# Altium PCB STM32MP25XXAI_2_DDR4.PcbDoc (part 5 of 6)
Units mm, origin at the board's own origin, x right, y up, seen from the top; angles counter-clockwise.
Board outline 172 x 137 mm, 4 copper layers (Top Layer, Signal Layer 1, Signal Layer 2, Bottom Layer), stack 1.614 mm thick; 241 components, 153 nets, 1312 pads, 924 vias.
Unrouted connection lines stored in the file: 13.
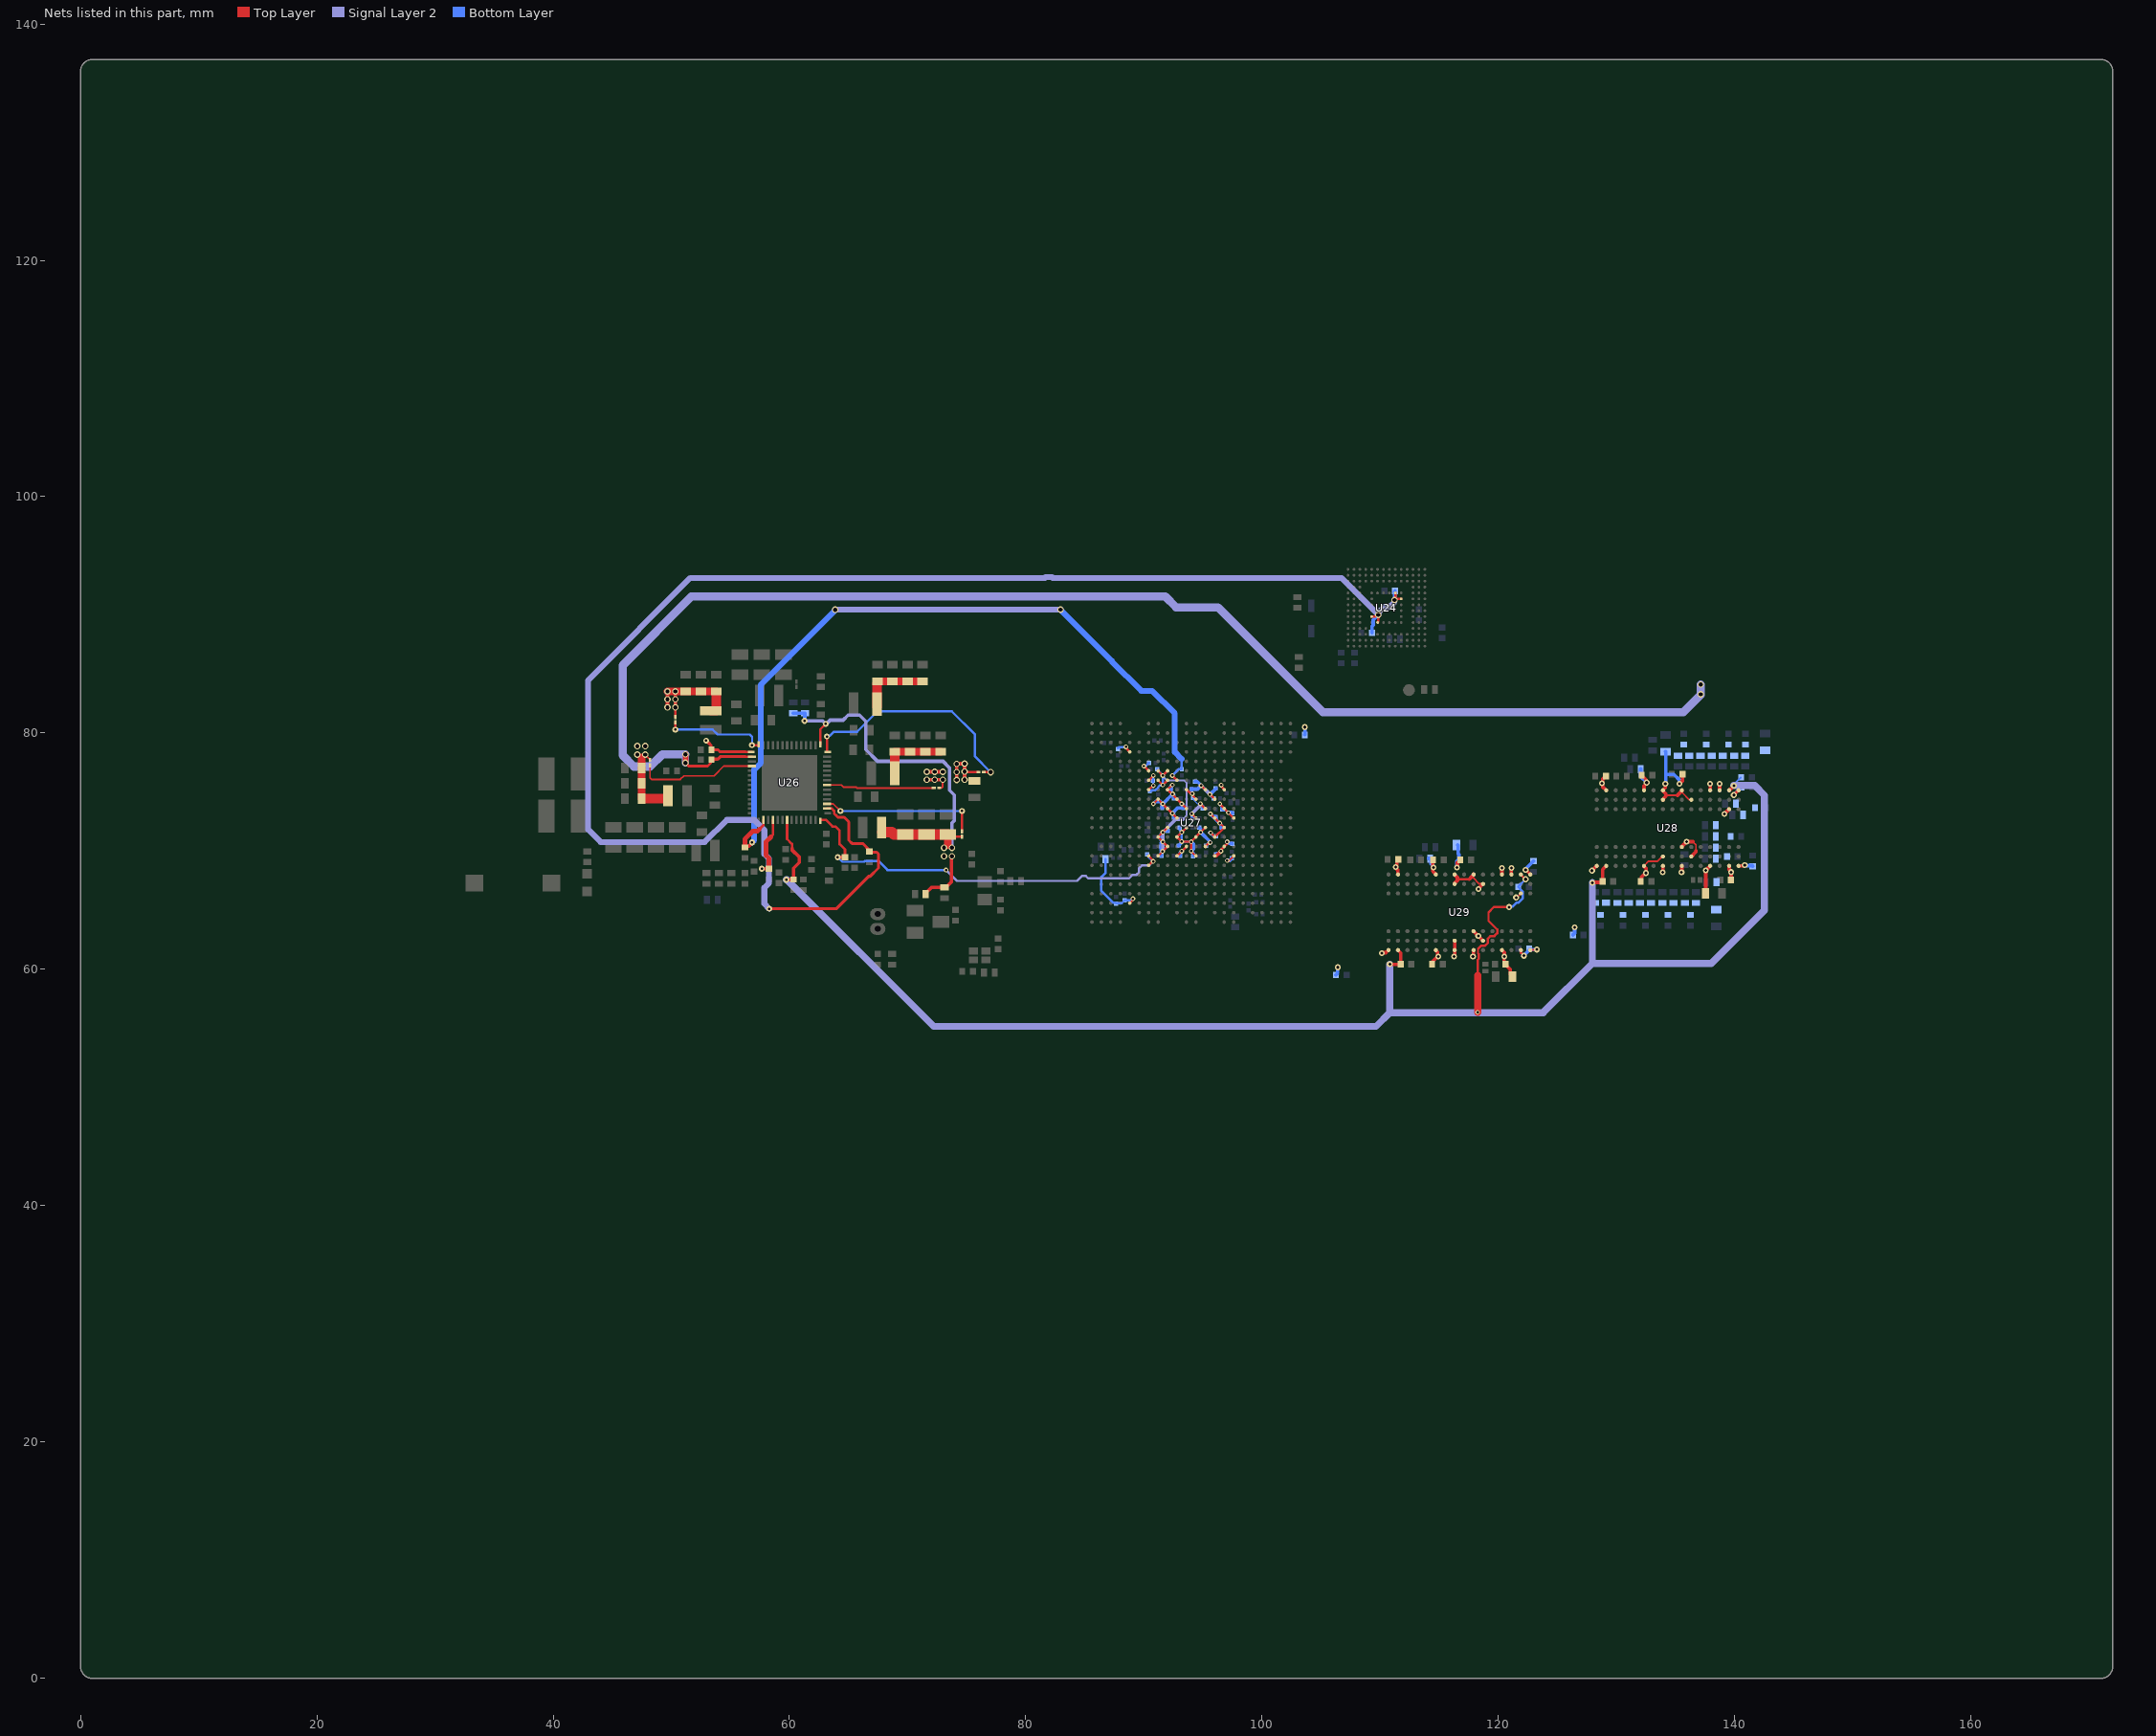
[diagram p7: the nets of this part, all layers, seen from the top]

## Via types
v1: diameter 0.55, hole 0.35, Top Layer to Bottom Layer, 432 vias
v2: diameter 0.4, hole 0.2, Top Layer to Bottom Layer, tented both sides, 202 vias
v3: diameter 0.5, hole 0.2, Top Layer to Bottom Layer, 146 vias
v4: diameter 0.5, hole 0.25, Top Layer to Bottom Layer, 144 vias

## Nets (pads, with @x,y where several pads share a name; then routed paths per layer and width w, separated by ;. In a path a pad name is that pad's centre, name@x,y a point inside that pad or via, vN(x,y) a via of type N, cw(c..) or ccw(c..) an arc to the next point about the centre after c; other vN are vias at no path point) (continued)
VDD_DDR: C39.2 C41.2 C48.2 C50.2 C51.2 C53.2 C54.1 C55.2 C56.2 C57.2 C58.2 C59.2 C60.2 C76.2 C77.2 C80.2 C82.2 C84.2 C85.2 C93.2 C94.2 C99.2 C200.2 C202.2 C236.2 C238.2 C247.2 C261.2 C262.2 C264.2 C276.2 C278.2 C279.2 L5.2 LNK8.2 R300.2 R302.2 U26.43 U27.K15 U27.L14 U27.L16 U27.M15 U27.N14 U27.P15 U27.R14 U27.R16 U28.A1 U28.A9 U28.B3 U28.B9 U28.C1 U28.D1 U28.D9 U28.F2 U28.F8 U28.G1 U28.G7 U28.G9 U28.J1 U28.J2 U28.J8 U28.J9 U28.L1 U28.L9 U28.R1 U28.T9 U29.A1 U29.A9 U29.B3 U29.B9 U29.C1 U29.D1 U29.D9 U29.F2 U29.F8 U29.G1 U29.G7 U29.G9 U29.J1 U29.J2 U29.J8 U29.J9 U29.L1 U29.L9 U29.R1 U29.T9 | length 80.3
  Top Layer w0.09: U29.J8@116.269,62.399 U29.J8@116.269,62.424 ; 135.525,74.975 U28.G1@135.525,75.094
  Top Layer w0.1: U27.R16@97.575,69.6 U27.R16@97.6,69.6
  Top Layer w0.15: v1(47.798,78.165) 48.2,77.763 LNK8.2@48.2,77.723 ; 117.718,67.815 117.757,67.815 117.797,67.775 117.845,67.775 118.389,67.232 118.694,67.232 U29.F2@118.7,67.225 ; U29.G1@117.9,67.998 U29.G1@117.9,68.025 ; v4@121.5,66.054 121.514,66.054 121.885,66.425 U29.B3@121.9,66.425 ; U28.L9@132.325,68.75 132.325,68.775 132.7,69.15 133.475,69.15 U28.J8@133.936,69.611 ; 134.158,74.728 135.167,74.728 ; 135.525,74.975 136.15,74.35 U28.F2@136.325,74.35 ; 136.45,70.8 136.725,70.525 136.725,70.05
  Top Layer w0.2: v2@95.6,73.15 v2(95.625,73.15) 95.65,73.15 U27.L14@96,72.8 v2(96.42,72.379) ; v2@95.625,71.575 U27.N14@96,71.2 U27.M15@96.8,72 v2@96.421,72.379 ; v2@96.4,74 U27.K15@96.8,73.6 v2(97.15,73.25) ; v2(96.525,70) 96.563,70.038 96.563,70.163 U27.P15@96.8,70.4 97.05,70.65 v2(97.05,70.8) ; v2(97.05,69.2) 97.2,69.2 U27.R16@97.6,69.6 ; v2@97.125,73.275 v2(97.15,73.25) ; U27.L16@97.6,72.8 v2(97.15,73.25) ; 116.526,67.625 117.535,67.625 ; U29.B9@121.9,61.625 121.906,61.619 121.906,61.394 v4(122.15,61.15) ; U29.A9@122.7,61.625 122.725,61.65 123.225,61.65 v4(123.25,61.675)
  Top Layer w0.21: 56.275,78.4 U26.43@56.825,78.4
  Top Layer w0.25: 53.195,79.125 53.199,79.125 53.345,78.979 53.345,78.685 C39.2@53.455,78.575 ; C39.2@53.505,78.575 53.975,78.575 54.15,78.4 56.275,78.4
  Top Layer w0.3: v3@52.944,79.376 53.195,79.125 ; U27.R14@96,69.6 96.125,69.6 v2(96.525,70) ; v4@110.105,61.41 v4(110.144,61.372) 110.182,61.41 110.459,61.41 110.673,61.625 U29.T9@110.7,61.625 ; U29.R1@111.5,68.025 111.481,68.044 111.481,68.415 111.3,68.596 v4(111.3,68.65) 111.3,68.704 111.42,68.824 111.42,69.195 C77.2@111.525,69.3 ; C94.2@114.356,60.385 C94.2@114.394,60.422 ; C76.2@114.45,69.197 114.45,68.6 114.45,68.3 114.7,68.05 U29.L1@114.7,68.025 ; C94.2@114.468,60.697 114.846,61.075 v4(114.9,61.075) 114.862,61.113 114.862,61.436 114.7,61.598 U29.L9@114.7,61.625 ; v4(116.25,61.075) 116.3,61.125 U29.J9@116.3,61.625 U29.J8@116.3,62.425 ; U29.J2@116.3,67.225 116.32,67.244 116.32,67.317 116.526,67.524 116.526,67.625 116.526,67.772 116.3,67.998 U29.J1@116.3,68.025 ; v4@116.492,68.629 116.538,68.675 116.538,69.013 116.775,69.25 C80.2@116.775,69.275 ; 117.535,67.625 117.535,67.632 117.718,67.815 U29.G1@117.9,67.998 ; v4(117.85,61.075) 117.85,61.129 117.891,61.17 117.891,61.615 U29.G9@117.9,61.625 ; U29.G1@117.881,68.044 U29.G1@117.9,68.025 ; v4@117.896,61.08 v4@117.9,61.084 ; U29.G7@117.9,63.225 117.9,63.213 117.913,63.213 v4(118.3,62.825) ; v4@118.3,62.813 v4(118.3,62.825) ; v4(118.325,66.8) 118.325,66.837 118.7,67.213 U29.F2@118.7,67.225 ; U29.F8@118.7,62.425 v4(118.3,62.825) ; U29.D9@120.3,61.625 120.5,61.425 v4(120.5,61.075) 120.47,61.045 120.47,60.53 C93.2@120.825,60.175 ; U29.D1@120.3,68.025 v4(120.3,68.575) ; C93.2@120.6,60.425 120.6,60.4 121.005,59.995 121.005,59.57 C99.2@121.175,59.4 ; U29.C1@121.1,68.025 v4(121.1,68.575) ; v4(122.3,68.425) U29.A1@122.7,68.025 ; v4(127.927,68.35) 128.305,68.728 U28.T9@128.332,68.728 ; C51.2@129.095,76.371 129.095,76.346 128.813,76.065 128.813,75.788 v4(128.775,75.75) 128.813,75.712 128.813,75.462 U28.R1@129.125,75.15 ; C84.2@132.025,67.425 C84.2@132.05,67.45 132.1,67.499 132.1,67.8 132.478,68.178 132.497,68.178 v4@132.5,68.175 ; C50.2@132.125,76.425 132.125,76.4 132.23,76.295 132.255,76.295 132.512,76.038 132.512,75.838 v4(132.55,75.8) 132.55,75.749 132.325,75.524 U28.L1@132.325,75.15 ; U28.L9@132.332,68.701 132.5,68.533 v4@132.5,68.175 ; v4(132.5,68.15) v4@132.5,68.175 ; v4(133.9,68.2) 133.925,68.225 U28.J9@133.925,68.75 ; U28.J1@133.925,75.15 134.125,75.35 v4(134.125,75.7) ; U28.J2@133.932,74.328 133.951,74.347 133.951,74.42 134.158,74.627 134.158,74.728 134.158,74.875 U28.J1@133.932,75.101 ; 135.167,74.728 135.167,74.735 U28.G1@135.525,75.094 ; v4(135.325,75.7) 135.575,75.95 C48.2@135.575,76.375 ; v4(135.5,68.2) 135.525,68.225 U28.G9@135.525,68.75 ; U28.G7@135.525,70.35 135.525,70.4 v4(135.925,70.8) 136.45,70.8 ; U28.F8@136.325,69.55 136.725,69.95 136.725,70.05 ; C85.2@137.525,66.425 137.542,66.442 137.542,68.367 v4(137.55,68.375) 137.903,68.728 U28.D9@137.932,68.728 ; U28.D1@137.932,75.128 v4@137.932,75.678 ; U28.C1@138.732,75.128 v4@138.732,75.678 ; v4(139.125,73.15) U28.B3@139.525,73.55 ; U28.B9@139.525,68.75 139.535,68.74 139.535,68.445 139.7,68.279 v4(139.7,68.225) 139.688,68.213 139.688,67.563 C82.2@139.675,67.55 ; v4(139.925,74.75) U28.A1@140.325,75.15 ; U28.A9@140.325,68.75 140.335,68.76 140.73,68.76 140.796,68.825 v4(140.85,68.825)
  Top Layer w0.64: C202.2@47.475,74.45 C41.2@47.475,75.75 C200.2@47.475,77.05 ; 47.475,77.495 47.475,77.925
  Top Layer w0.8: C202.2@47.7,74.45 L5.2@49.475,74.45
  Signal Layer 2 w0.3: v2@96.356,72.394 96.406,72.394 v2@96.425,72.375
  Bottom Layer w0.09: C279.2@140.55,75.425 C279.2@140.575,75.4
  Bottom Layer w0.2: v2@96.4,74 96.4,73.946 96.549,73.796 96.549,73.599 C60.2@96.624,73.524 ; C60.2@96.631,73.524 96.704,73.452 96.933,73.452 97.135,73.25 v2(97.15,73.25) ; v2@97.125,73.275 v2(97.15,73.25) ; v2@97.15,73.23 v2(97.15,73.25)
  Bottom Layer w0.3: v2@95.6,71.575 95.9,71.275 C55.2@96.1,71.275 ; v2@95.6,73.15 v2(95.625,73.15) ; v2@95.627,73.15 v2(95.625,73.15) ; C59.2@96.1,69.725 96.175,69.8 96.308,69.8 96.508,70 v2(96.525,70) ; v2(96.42,72.379) 96.394,72.379 96.124,72.649 96.124,72.687 96.099,72.712 96.099,72.85 C56.2@96.074,72.875 96.049,72.9 95.875,72.9 v2(95.625,73.15) ; v2@96.425,72.375 96.425,72.347 96.549,72.223 96.549,71.999 C57.2@96.574,71.974 ; v2@97.023,70.8 v2(97.05,70.8) 97.077,70.8 97.227,70.65 97.45,70.65 C54.1@97.475,70.625 ; v2(97.05,69.2) 97.069,69.219 97.269,69.219 C53.2@97.45,69.4 ; v2@97.125,73.275 97.425,73.275 C58.2@97.5,73.2 ; C276.2@103.62,79.846 103.625,79.851 v4(103.625,80.5) ; C264.2@106.25,59.525 106.4,59.675 v4(106.4,60.175) ; R300.2@114.1,69.38 114.205,69.275 114.305,69.175 114.305,68.947 114.462,68.79 114.462,68.663 v4(114.5,68.625) ; v4@116.5,68.575 116.492,68.583 116.492,69.16 116.65,69.318 116.65,69.732 116.596,69.787 116.596,70.479 C236.2@116.55,70.525 ; v4@122.075,61.1 122.65,61.675 v4(123.25,61.675) ; v4(122.3,68.425) 122.339,68.463 122.339,68.538 122.95,69.15 C247.2@122.975,69.15 ; C261.2@126.3,62.9 126.45,63.05 v4(126.45,63.55) ; R302.2@132.05,76.95 132.05,76.3 v4(132.55,75.8) ; v4(134.125,75.7) 134.166,75.741 134.166,76.487 ; C278.2@134.15,78.425 134.166,78.409 134.166,76.873 134.166,76.487 ; 134.166,76.114 134.166,76.487 ; v4(135.325,75.7) 135.325,76.025 134.864,76.487 134.166,76.487 ; v4(139.925,74.75) 139.925,74.8 140.55,75.425 C279.2@140.438,75.313 ; v4@140.875,68.775 141.475,68.775 C238.2@141.525,68.725
  other v1: 47.123,78.165 47.123,78.89 47.798,78.89
  other v2: 95.65,71.55 96.425,74
  other v3: 52.95,79.348
  other v4: 121.5,66.08 116.5,68.625 137.925,75.7 138.725,75.7
VDD_DDR_FB: LNK8.1 U26.46 | length 10.2
  Top Layer w0.15: LNK8.1@48.2,77.273 48.2,76.19 48.317,76.073 50.767,76.073 51.067,76.373 51.737,76.373 51.739,76.375 53.627,76.375 54.452,77.2 U26.46@56.83,77.2
VDD_EMMC: C177.2 C180.2 C190.1 U24.E6 U24.F5 U24.J10 U24.K9 U26.16 | length 133.6
  Top Layer w0.2: U24.E6@109.275,89.85 109.58,89.85 109.73,90 v1(109.825,90) ; U24.F5@109.775,89.35 109.775,89.358 109.825,89.408 v1@109.825,89.85 ; v1(111.2,91.25) v1@111.275,91.325 ; U24.J10@111.275,91.85 111.275,91.42 111.267,91.412 111.267,91.333 v1@111.275,91.325 ; U24.K9@111.775,91.35 111.395,91.35 111.362,91.317 111.283,91.317 v1@111.275,91.325
  Top Layer w0.21: U26.16@63.17,73.6 63.6,73.6 63.788,73.412 63.788,73.188 63.934,73.041
  Top Layer w0.25: v3(58.3,65.125) 63.96,65.125 66.7,67.865 66.822,67.865 67.535,68.578 67.535,69.764 67.389,69.91 66.805,69.91 C190.1@66.75,69.965 ; 63.932,73.038 64.098,72.872 64.628,72.872 65.025,72.475 65.025,70.925 65.3,70.65 66.195,70.65 C190.1@66.75,70.095
  Signal Layer 2 w0.5: v3(58.3,65.125) 57.872,65.553 57.872,66.908 58.265,67.301 58.265,69.369 57.872,69.762 57.872,71.786 57.009,72.649 54.703,72.649 52.827,70.773 44.024,70.773 42.958,71.839 42.958,84.457 51.616,93.115 81.606,93.115 81.691,93.2 82.209,93.2 82.294,93.115 85.406,93.115 85.416,93.125 85.934,93.125 85.944,93.115 106.726,93.115 v1@109.678,90.163 ; v1(109.825,90) 109.835,90.01 109.835,90.196 110.259,90.62 110.475,90.62 110.737,90.62 111.2,91.083 v1(111.2,91.25)
  Bottom Layer w0.3: C180.2@109.3,88.475 109.3,89.049 109.4,89.149 109.4,89.575 v1(109.825,90) ; v1(111.2,91.25) 111.225,91.275 111.225,92 C177.2@111.25,92.025
VDD_SDCARD: C142.1 U26.4 | length 5.1
  Top Layer w0.21: 58.425,71.2 58.6,71.375 U26.4@58.6,72.63
  Top Layer w0.3: v3(57.665,68.51) C142.1@58.275,68.51
  Top Layer w0.4: C142.1@58.275,68.51 58.275,69.393 58.01,69.658 58.01,70.785 58.425,71.2
VDDA1V8_AON: C189.2 C234.2 U26.14 U27.R7 U27.T7 | length 35.8
  Top Layer w0.2: U27.T7@90.4,68.8 90.687,69.087 90.757,69.087 v2(90.795,69.125) 90.795,69.178 90.4,69.573 U27.R7@90.4,69.6
  Top Layer w0.21: U26.14@62.6,72.63 63.11,72.63 63.648,72.092 63.887,72.092 64.245,71.734 64.245,70.602 64.7,70.147 C189.2@64.7,69.49
  Top Layer w0.3: v3(64.09,69.49) C189.2@64.7,69.49
  Signal Layer 2 w0.2: v2(73.253,68.406) 73.259,68.406 74.183,67.482 84.342,67.482 84.76,67.9 85.091,67.9 85.292,67.699 88.734,67.699 89.034,68 89.2,68 89.366,68 89.6,68.234 89.6,68.566 89.835,68.8 90.47,68.8 v2(90.795,69.125) v2@90.726,69.125
  Bottom Layer w0.2: v3(64.09,69.49) 64.48,69.1 66.321,69.1 66.392,69.171 67.535,69.171 68.3,68.406 v2(73.253,68.406) ; C234.2@90.275,69.735 90.441,69.569 90.441,69.443 90.76,69.125 v2(90.795,69.125)
VDDCORE: C1.1 C2.2 C3.2 C4.1 C5.2 C6.2 C22.2 C23.2 C24.2 C66.2 C69.2 C70.2 C183.2 L2.2 LNK2.2 R249.1 U27.D5 U27.F7 U27.G7 U27.H7 U27.H9 U27.J8 U27.J10 U27.K9 U27.K11 U27.L10 | length 26.2
  Top Layer w0.2: C22.2@71.275,84.375 C22.2@71.323,84.423 ; v1@74.87,76.685 LNK2.2@75.98,76.685 ; v2(88.475,78.825) 88.475,78.725 U27.D5@88.8,78.4 ; v2(90,77.2) U27.F7@90.4,76.8 U27.F7@90.425,76.8 ; U27.H7@90.4,75.2 90.425,75.2 90.775,75.55 v2(90.8,75.55) ; U27.G7@90.4,76 v2(90.8,76.4) ; v2(90.8,74) U27.J8@91.2,74.4 v2(91.6,74) v2(92.4,73.2) U27.L10@92.8,72.8 ; v2(92.4,75.6) U27.H9@92,75.2 v2@92.425,74.775 ; v2(92.425,74.85) v2@92.425,74.775 ; U27.K11@93.6,73.6 v2(93.2,74) U27.J10@92.8,74.4 v2@92.425,74.775
  Top Layer w0.3: v1@74.151,77.404 v1(74.826,77.404) v1(74.826,76.729) ; v1(74.156,76.024) v1(74.156,76.699) v1(74.156,77.374) ; v1(74.826,76.054) v1(74.826,76.729) ; v1@74.87,76.685 v1(74.826,76.729)
  Top Layer w0.64: C183.2@67.45,84.375 C24.2@68.725,84.375 C23.2@70,84.375 C22.2@71.275,84.375
  Top Layer w0.8: L2.2@67.415,82.2 L2.2@67.415,82.45 C183.2@67.415,84.173
  Bottom Layer w0.2: C70.2@87.8,78.7 87.9,78.8 88.038,78.8 v2@88.4,78.8 ; v2(90,77.2) 90.038,77.238 90.188,77.238 C66.2@90.425,77.475 ; v2(90.8,75.55) 90.777,75.572 90.777,75.948 C69.2@90.755,75.97 90.777,75.992 90.777,76.378 v2(90.8,76.4)
  Bottom Layer w0.3: v2(90.8,74) 91,74.2 91.4,74.2 v2(91.6,74) ; C3.2@91.55,73.65 91.55,73.95 v2(91.6,74) ; v2(92.4,75.6) 92.275,75.475 C4.1@92.275,75.25 92.275,75 v2(92.425,74.85) ; C1.1@92.55,72.825 92.55,73.05 v2(92.4,73.2) 92.85,73.65 C2.2@93.326,73.65 93.325,73.875 v2(93.2,74) ; C5.2@92.551,74.475 92.55,74.725 v2(92.425,74.85) ; v2(91.6,74) 92.425,74.825 v2(92.425,74.85)
VDDCORE_FB: LNK2.1 U26.28 | length 19.9
  Top Layer w0.2: U26.28@63.17,78.4 v3(63.17,79.7) ; LNK2.1@76.444,76.687 v1@77.031,76.685
  Bottom Layer w0.2: v3(63.17,79.7) 63.227,79.757 63.401,79.757 63.754,80.111 65.734,80.111 67.457,81.833 73.744,81.833 75.675,79.902 75.675,78.041 v1(77.033,76.683)
VDDCPU: C13.1 C14.2 C15.2 C16.1 C17.2 C25.2 C26.2 C27.2 C28.2 C31.2 L3.2 LNK4.1 U27.H11 U27.H13 U27.H15 U27.J12 U27.J14 U27.K13 U27.L12 | length 21.1
  Top Layer w0.2: LNK4.1@50.35,81.35 v1(50.35,82.173) ; U27.H11@93.6,75.2 93.627,75.2 93.924,74.903 94.052,74.903 94.128,74.827 94.128,74.699 94.4,74.427 U27.J12@94.4,74.4 ; v2(94.045,73.155) U27.L12@94.4,72.8 ; v2(94.775,74.005) 95.18,73.6 U27.K13@95.2,73.6 ; v2(94.845,75.555) U27.H13@95.2,75.2 ; v2(95.595,74.805) U27.J14@96,74.4 ; v2(96.54,75.591) 96.578,75.553 96.578,75.449 96.8,75.227 U27.H15@96.8,75.2
  Top Layer w0.3: v1(49.675,82.173) v1(49.675,82.848) v1(49.675,83.523) v1(50.35,83.523) v1(50.35,82.848) v1(50.35,82.173)
  Top Layer w0.64: v1(49.675,83.523) 49.675,83.525 C27.2@51.2,83.525 C28.2@52.5,83.525 C26.2@53.8,83.525
  Top Layer w0.8: L3.2@53.35,81.875 53.8,81.875 53.8,83.173
  Signal Layer 2 w0.3: v2(94.045,73.155) 94.756,73.866 94.756,73.986 v2(94.775,74.005) ; v2(94.845,75.555) v2(95.595,74.805)
  Bottom Layer w0.1: C14.2@94.15,74.48 94.15,74.379 94.524,74.005 v2(94.775,74.005)
  Bottom Layer w0.2: v2(94.045,73.155) 94.045,72.855 C31.2@94.125,72.775 ; v2@94.775,73.978 v2(94.775,74.005) ; C13.1@94.95,73.625 94.95,73.803 ; v2(95.595,74.805) 95.633,74.767 95.633,74.692 C15.2@95.875,74.45
  Bottom Layer w0.3: v2(94.095,74.865) 94.095,74.892 94.05,74.937 94.05,75.225 C25.2@94.025,75.25 94.548,75.25 v2@94.853,75.555 ; C17.2@94.325,75.875 94.525,75.875 v2(94.845,75.555) ; v2@94.775,73.978 94.95,73.803 ; v2(95.595,74.805) C16.1@96.095,75.305
VDDCPU_FB: LNK4.2 U26.42 | length 8.6
  Top Layer w0.2: v3(50.35,80.29) LNK4.2@50.35,80.9 ; v3(56.825,78.975) U26.42@57.395,78.975
  Bottom Layer w0.2: v3@50.37,80.287 53.499,80.287 53.914,79.872 56.643,79.872 56.845,79.67 v3@56.845,78.972
VDDGPU: C7.2 C8.2 C9.2 C10.2 C11.1 C12.2 C34.2 C35.2 C36.2 C37.2 L4.2 LNK7.2 U27.M11 U27.M13 U27.N10 U27.N12 U27.P13 U27.R12 | length 21.3
  Top Layer w0.15: LNK7.2@72.675,75.35 72.682,75.358 72.885,75.358 72.973,75.445 v1(72.973,76.038)
  Top Layer w0.2: C35.2@73.05,78.393 C35.2@73.098,78.345 ; U27.M11@93.6,72 v2(93.2,71.6) U27.N10@92.8,71.2 93.197,70.803 93.997,70.803 v2(94,70.8) ; U27.R12@94.4,69.6 v2(94,70) v2(94,70.8) ; U27.P13@95.2,70.4 95.487,70.687 95.562,70.687 v2(95.6,70.725) ; U27.M13@95.2,72 v2(94.8,71.6) v2(94,70.8)
  Top Layer w0.3: v1(71.623,76.038) v1(72.298,76.038) v1(72.973,76.038) ; v1(71.623,76.713) v1(72.298,76.713) v1(72.973,76.713)
  Top Layer w0.64: C37.2@68.9,78.4 C36.2@70.2,78.4 C34.2@71.5,78.4 C35.2@72.8,78.4
  Top Layer w0.8: L4.2@68.925,76.6 68.925,78.073
  Bottom Layer w0.2: C9.2@93.025,72 93.025,71.775 v2(93.2,71.6) 93.197,71.598 93.197,70.808 93.195,70.805 93.197,70.803 93.997,70.803 v2(94,70.8) ; v2(95.6,70.725) v2@95.61,70.715
  Bottom Layer w0.3: C10.2@92.95,70.48 93.176,70.706 93.176,70.786 v2@93.195,70.805 ; v2(94,70.8) 94.175,70.625 94.175,70.175 v2(94,70) 94.2,69.8 C12.2@94.2,69.575 ; C7.2@94.675,72 94.8,71.875 v2(94.8,71.6) 94.833,71.567 95.581,70.819 95.581,70.744 v2(95.6,70.725) 95.581,70.706 95.506,70.706 C11.1@95.25,70.45
  other v2: 93.2,70.805
VDDGPU_FB: LNK7.1 U26.21 | length 9.3
  Top Layer w0.15: U26.21@63.05,75.6 64.383,75.6 64.56,75.423 65.64,75.423 65.713,75.35 LNK7.1@72.225,75.35
VDDIO: C19.2 C44.1 C45.2 C46.2 C47.1 C52.2 C73.2 C74.2 C186.2 C187.2 L6.2 LNK11.2 R27.2 R67.2 R260.2 R261.2 U26.29 U27.F8 U27.F9 U27.G8 U27.G9 U27.M9 U27.N8 U27.P9 U27.P11 U27.R8 U27.R10 | length 61.4
  Top Layer w0.2: U26.29@62.6,79.045 62.6,80.298 v3(63.075,80.773) ; C186.2@73.4,71.4 73.585,71.215 LNK11.2@74.6,71.215 ; U27.R8@91.2,69.6 v2(91.575,69.975) U27.P9@92,70.4 v2(91.6,70.8) U27.N8@91.2,71.2 v2(91.6,71.6) U27.M9@92,72 ; U27.G8@91.2,76 91.599,75.6 U27.G9@92,76 ; U27.F8@91.2,76.8 v2(91.6,76.4) U27.F9@92,76.8 ; U27.R10@92.8,69.6 v2(93.2,70) U27.P11@93.6,70.4
  Top Layer w0.3: R67.2@71.525,66.375 71.525,66.44 72.01,66.925 R27.2@73.125,66.925 73.23,67.03 73.339,67.03 73.712,67.402 73.712,69.52 v1(73.752,69.56) ; v1(73.077,69.56) v1@73.125,69.512
  Top Layer w0.64: 73.4,70.525 C186.2@73.4,70.955
  Top Layer w0.9: L6.2@67.85,71.6 68.65,71.6 68.85,71.4 C187.2@69.8,71.4 C19.2@71.6,71.4 C186.2@73.4,71.4
  Signal Layer 2 w0.15: v2(91.599,75.599) 91.971,75.971 91.962,75.98 ; v2@91.6,76.338 v2@91.6,76.342 ; v2(91.6,76.4) v2@91.6,76.342 ; 93.301,72.703 93.608,73.01 93.608,75.783 93.411,75.98 91.962,75.98 ; v2@91.6,76.342 91.962,75.98
  Signal Layer 2 w0.3: v3(61.284,81.027) 62.799,81.027 63.05,80.776 v3@63.075,80.776 ; v3(63.075,80.773) 63.129,80.773 63.44,81.084 64.543,81.084 64.973,81.513 65.931,81.513 66.455,80.989 66.455,78.601 67.456,77.6 72.999,77.6 73.551,77.048 73.551,75.156 73.951,74.756 73.951,72.573 73.752,72.375 v1(73.752,70.285) ; v2(91.575,69.975) 91.6,70 v2(91.6,71.6) 92.703,72.703 93.301,72.703
  Bottom Layer w0.2: C74.2@90.5,75.05 90.575,75.125 90.667,75.125 90.692,75.15 90.931,75.15 90.946,75.165 90.981,75.165 91.2,75.384 91.2,75.419 91.342,75.561 91.561,75.561 v2(91.599,75.599) 91.6,76.4 91.6,76.45 C73.2@91.125,76.925
  Bottom Layer w0.3: R260.2@60.33,81.68 R261.2@61.305,81.68 61.294,81.669 61.294,81.038 v3(61.284,81.027) ; C44.1@91.475,69.6 91.475,69.875 v2(91.575,69.975) 91.475,70.075 91.475,70.675 v2(91.6,70.8) 91.475,70.925 91.475,71.475 91.725,71.725 C46.2@92.025,71.725 ; C45.2@93.075,69.6 93.075,69.875 v2(93.2,70) v2@93.225,70
  other v1: 73.077,70.285
VDDIO_FB: LNK11.1 U26.17 | length 13.4
  Top Layer w0.15: U26.17@63.17,74 63.7,74 64.303,73.397 v3(64.315,73.397)
  Top Layer w0.2: LNK11.1@74.6,71.665 v3(74.6,73.4)
  Bottom Layer w0.15: v3(64.315,73.397) v3@74.597,73.397
VDDIO_SDCARD: C71.2 C217.1 U26.2 U27.G10 | length 65.5
  Top Layer w0.2: v2(92.4,76.4) U27.G10@92.8,76
  Top Layer w0.21: 57.459,71.873 57.8,72.214 U26.2@57.8,72.63
  Top Layer w0.3: C217.1@56.225,70.38 56.27,70.425 56.559,70.425 56.835,70.701 v3(56.835,70.737)
  Top Layer w0.4: C217.1@56.225,70.32 56.225,70.38 56.225,71.015 56.899,71.69 57.275,71.69 57.459,71.873
  Signal Layer 2 w0.5: v1(63.865,90.43) 63.867,90.432 82.942,90.432 v1(82.945,90.435)
  Bottom Layer w0.2: v2(92.4,76.4) 92.95,76.95 C71.2@93.201,76.95 93.201,77.799
  Bottom Layer w0.5: v3(56.835,70.737) 57.009,70.911 57.009,76.91 57.581,77.482 57.581,81.596 57.575,81.601 57.575,82.099 57.581,82.104 57.581,84.092 63.855,90.367 63.855,90.42 v1(63.865,90.43) ; v1@82.945,90.444 v1(82.945,90.435) 87.294,86.086 87.294,86.055 89.779,83.57 90.696,83.57 92.605,81.661 92.605,78.395 93.2,77.8
VPP_DDR: C83.2 C91.1 C95.2 C245.2 C277.2 U26.7 U28.B1 U28.R9 U29.B1 U29.R9 | length 143.8
  Top Layer w0.09: U28.B1@139.526,75.127 U28.B1@139.602,75.127
  Top Layer w0.2: 118.242,59.475 118.242,60.789 118.35,60.898 118.35,61.271 118.275,61.346 118.275,61.73 118.545,62 118.879,62 119.115,62.236 119.115,62.6 119.334,62.819 119.665,62.819 119.9,63.053 119.9,63.368 119.166,64.102 119.166,64.816 119.62,65.27 v4(120.9,65.27) ; U29.B1@121.9,68.011 v4@122.287,67.625
  Top Layer w0.21: U26.7@59.8,72.63 59.8,71.025 60.215,70.61 60.215,70.253
  Top Layer w0.28: v4(110.809,60.424) C95.2@111.49,60.424 ; C95.2@111.49,60.425 C95.2@111.725,60.425 111.725,61.4 U29.R9@111.5,61.625 U29.R9@111.5,61.575 ; C83.2@128.825,67.45 128.825,68.45 U28.R9@129.125,68.75
  Top Layer w0.3: v3(59.74,67.58) C91.1@60.35,67.58 ; 60.215,70.253 60.215,70.118 60.835,69.498 60.835,69.035 60.35,68.55 C91.1@60.35,67.73 ; v4@127.925,67.325 127.96,67.36 128.735,67.36 C83.2@128.825,67.45 ; U28.B1@139.532,75.128 v4@139.932,75.528
  Top Layer w0.6: v2(118.242,56.366) 118.242,59.475
  Signal Layer 2 w0.6: v3(59.74,67.58) 59.793,67.58 72.203,55.171 109.646,55.171 110.809,56.334 ; v4(110.809,60.424) 110.809,56.334 ; 123.801,56.334 110.809,56.334 ; 123.801,56.351 127.95,60.5 ; v4(127.95,67.325) 127.95,60.5 ; v4@139.93,75.546 141.709,75.546 142.522,74.733 142.522,65.002 138.02,60.5 127.95,60.5
  Bottom Layer w0.09: v4(139.925,75.55) v4@139.925,75.65 ; C277.2@140.5,76.225 C277.2@140.55,76.225
  Bottom Layer w0.15: v4@139.925,75.65 C277.2@140.5,76.225
  Bottom Layer w0.2: v4(120.9,65.27) 120.957,65.327 121.217,65.327 121.519,65.63 121.686,65.63 122.072,66.016 122.072,66.553 121.83,66.795 121.83,66.82 C245.2@121.675,66.975 121.675,67 v4(122.3,67.625)
VREF+: C67.2 C68.2 R269.2 U27.Y5 | length 6.6
  Top Layer w0.2: U27.Y5@88.8,65.6 89.037,65.837 89.037,65.942 v2(89.076,65.981)
  Bottom Layer w0.2: R269.2@86.754,69.315 86.754,68.159 86.402,67.808 86.402,66.63 87.387,65.645 87.585,65.645 87.63,65.6 88.125,65.6 C68.2@88.375,65.85 88.904,65.85 89.035,65.981 v2(89.076,65.981)
VTT_DDR: C40.2 C211.2 C226.2 C239.2 C254.2 C255.2 C256.2 C257.2 C258.2 C259.2 C280.2 C281.2 C282.2 C283.2 C284.2 R253.2 R254.2 R255.2 R256.2 R257.2 R258.2 R259.2 R263.2 R264.2 R265.2 R266.2 R268.2 R271.2 R273.2 R275.2 R276.2 R277.2 R278.2 R279.2 R280.2 R281.2 R282.2 R283.2 R284.2 U26.44 | length 120.6
  Top Layer w0.21: 56.275,78 U26.44@56.83,78
  Top Layer w0.25: v1(51.2,78.198) v1@51.202,78.196 ; v1@51.225,77.473 v1(51.202,77.473) 51.475,77.2 53.075,77.2 53.32,77.445 53.32,77.635 53.435,77.75 C40.2@53.505,77.75 ; C40.2@53.51,77.635 53.665,77.79 53.94,77.79 54.15,78 56.275,78
  Top Layer w0.5: v1(51.202,77.473) v1@51.202,78.196
  Signal Layer 2 w0.6: v1@51.2,77.475 v1(51.2,78.198)
  Signal Layer 2 w0.7: v1(51.2,78.198) 49.244,78.198 48.209,77.163 46.837,77.163 45.883,78.117 45.883,85.733 51.699,91.549 91.801,91.549 92.714,90.636 96.269,90.636 105.136,81.769 135.665,81.769 137.125,83.229 v1(137.125,83.275) v1(137.125,84.1)
pads on no net: U24.A1 U24.A2 U24.A7 U24.A8 U24.A9 U24.A10 U24.A11 U24.A12 U24.A13 U24.A14 U24.B1 U24.B7 U24.B8 U24.B9 U24.B10 U24.B11 U24.B12 U24.B13 U24.B14 U24.C1 U24.C3 U24.C5 U24.C7 U24.C8 U24.C9 U24.C10 U24.C11 U24.C12 U24.C13 U24.C14 U24.D1 U24.D2 U24.D3 U24.D4 U24.D12 U24.D13 U24.D14 U24.E1 U24.E2 U24.E3 U24.E5 U24.E8 U24.E9 U24.E10 U24.E12 U24.E13 U24.E14 U24.F1 U24.F2 U24.F3 U24.F10 U24.F12 U24.F13 U24.F14 U24.G1 U24.G2 U24.G3 U24.G10 U24.G12 U24.G13 U24.G14 U24.H1 U24.H2 U24.H3 U24.H12 U24.H13 U24.H14 U24.J1 U24.J2 U24.J3 U24.J12 U24.J13 U24.J14 U24.K1 U24.K2 U24.K3 U24.K6 U24.K7 U24.K10 U24.K12 U24.K13 U24.K14 U24.L1 U24.L2 U24.L3 U24.L12 U24.L13 U24.L14 U24.M1 U24.M2 U24.M3 U24.M7 U24.M8 U24.M9 U24.M10 U24.M11 U24.M12 U24.M13 U24.M14 U24.N1 U24.N3 U24.N6 U24.N7 U24.N8 U24.N9 U24.N10 U24.N11 U24.N12 U24.N13 U24.N14 U24.P1 U24.P2 U24.P7 U24.P8 U24.P9 U24.P10 U24.P11 U24.P12 U24.P13 U24.P14 U27.A2 U27.A3 U27.A4 U27.A7 U27.A8 U27.A11 U27.A12 U27.A15 U27.A16 U27.A21 U27.AA1 U27.AA2 U27.AA3 U27.AA4 U27.AA6 U27.AA7 U27.AA8 U27.AA10 U27.AA11 U27.AA12 U27.AA14 U27.AA15 U27.AA16 U27.AA18 U27.AA19 U27.AA20 U27.AA21 U27.AB2 U27.AB3 U27.AB4 U27.AB7 U27.AB8 U27.AB11 U27.AB12 U27.AB15 U27.AB16 U27.AB19 U27.AB20 U27.AB21 U27.B1 U27.B2 U27.B3 U27.B4 U27.B5 U27.B7 U27.B8 U27.B9 U27.B11 U27.B12 U27.B13 U27.B15 U27.B16 U27.B17 U27.B20 U27.B21 U27.C1 U27.C2 U27.C3 U27.C5 U27.C6 U27.C8 U27.C9 U27.C10 U27.C11 U27.C12 U27.C13 U27.C14 U27.C15 U27.C16 U27.C17 U27.C20 U27.D1 U27.D2 U27.D3 U27.D4 U27.D6 U27.D7 U27.D8 U27.D9 U27.D10 U27.D11 U27.D12 U27.D13 U27.D14 U27.D15 U27.D16 U27.D19 U27.E3 U27.E4 U27.E6 U27.E7 U27.E8 U27.E9 U27.E10 U27.E11 U27.E12 U27.E13 U27.E14 U27.E15 U27.E18 U27.F2 U27.F3 U27.F4 U27.F5 U27.F11 U27.F12 U27.F13 U27.F14 U27.F15 U27.G1 U27.G2 U27.G3 U27.G4 U27.G5 U27.G11 U27.G12 U27.G13 U27.G14 U27.G16 U27.H1 U27.H2 U27.H3 U27.H4 U27.H5 U27.H6 U27.J3 U27.J4 U27.J5 U27.J6 U27.J7 U27.J18 U27.K2 U27.K3 U27.K4 U27.K5 U27.K6 U27.K7 U27.K17 U27.L1 U27.L2 U27.L3 U27.L4 U27.L5 U27.L6 U27.L7 U27.L20 U27.M1 U27.M2 U27.M3 U27.M4 U27.M5 U27.M6 U27.N3 U27.N4 U27.N5 U27.N6 U27.P2 U27.P3 U27.P4 U27.P5 U27.R3 U27.R4 U27.R5 U27.R6 U27.T1 U27.T2 U27.T8 U27.T9 U27.T10 U27.T11 U27.T12 U27.T13 U27.T14 U27.T15 U27.T17 U27.T18 U27.U4 U27.U5 U27.U8 U27.U9 U27.U10 U27.U11 U27.U12 U27.U13 U27.U14 U27.U15 U27.U16 U27.U18 U27.U19 U27.V4 U27.V5 U27.V6 U27.V8 U27.V9 U27.V10 U27.V11 U27.V12 U27.V13 U27.V14 U27.V15 U27.V16 U27.V17 U27.W1 U27.W2 U27.W3 U27.W4 U27.W6 U27.W7 U27.W9 U27.W10 U27.W11 U27.W12 U27.W13 U27.W14 U27.W15 U27.W17 U27.Y1 U27.Y3 U27.Y4 U27.Y6 U27.Y7 U27.Y8 U27.Y9 U27.Y10 U27.Y11 U27.Y12 U27.Y13 U27.Y14 U27.Y15 U27.Y17 U27.Y18 U27.Y20 U28.P9 U28.T7 U29.P9 U29.T7
copper on no net: | length 335.7
  Top Layer w0.09: 81.172,76.702 85.898,76.702 86.105,76.495 88.305,76.495 88.8,76 ; 81.614,76.882 86.261,76.882 86.343,76.8 86.4,76.8 ; 81.76,77.09 86.513,77.09 86.803,76.8 87.2,76.8 ; 82.23,77.27 86.59,77.27 86.775,77.085 87.332,77.085 87.342,77.075 87.575,76.842 87.59,76.827 87.973,76.827 88,76.8 ; 82.334,77.52 86.693,77.52 86.898,77.315 87.427,77.315 87.437,77.305 87.657,77.085 88.515,77.085 88.8,76.8 ; 82.986,77.7 87.043,77.7 87.143,77.6 87.2,77.6 ; 83.083,77.935 87.665,77.935 88,77.6 ; 83.395,70.522 83.453,70.522 83.53,70.445 85.911,70.445 86.233,70.123 86.549,70.123 86.777,69.895 87.556,69.895 87.76,70.099 ; 83.448,70.265 85.754,70.265 86.124,69.895 86.522,69.895 86.817,69.6 87.2,69.6 ; 83.537,70.707 83.619,70.625 86.175,70.625 86.4,70.4 ; 83.604,70.895 83.694,70.805 86.412,70.805 86.695,70.522 86.695,70.28 86.9,70.075 87.406,70.075 87.731,70.4 88,70.4 ; 83.673,71.08 83.758,70.995 86.477,70.995 87.032,70.44 87.16,70.44 87.2,70.4 ; 83.685,78.115 85.718,78.115 86.003,78.4 86.4,78.4 ; 83.748,71.26 83.833,71.175 86.551,71.175 87.031,70.695 88.295,70.695 88.8,71.2 ; 83.789,78.365 85.565,78.365 85.6,78.4 ; 83.877,71.64 83.982,71.535 86.75,71.535 87.045,71.24 87.16,71.24 87.2,71.2 ; 84.075,71.875 84.235,71.715 86.827,71.715 87.047,71.495 88.295,71.495 88.8,72 ; 84.174,72.075 84.249,72 ; 84.615,68.995 85.224,68.995 85.354,69.125 87.525,69.125 88,69.6 ; 84.65,68.41 85.613,68.41 86.003,68.8 86.4,68.8 ; 84.862,74.565 86.439,74.565 86.939,75.065 87.011,75.065 87.146,75.2 87.2,75.2 ; 85.472,78.675 85.482,78.685 86.603,78.685 86.875,78.413 86.875,78.3 87.06,78.115 87.715,78.115 88,78.4 ; 85.472,78.925 85.482,78.915 86.642,78.915 87.157,78.4 87.2,78.4 ; 86.115,75.475 86.125,75.475 86.4,75.2 ; 86.865,75.665 87.2,76 ; 87.359,70.885 87.361,70.885 87.683,70.885 87.998,71.2 ; 87.424,60.877 89.925,63.377 89.925,64.197 90.105,64.377 90.105,65.305 90.4,65.6 ; 87.634,82.95 89.145,81.439 89.145,80.673 89.52,80.298 89.52,79.693 89.885,79.328 89.885,78.115 90.4,77.6 ; 87.634,60.832 90.105,63.303 90.105,64.122 90.4,64.417 90.4,64.8 ; 87.738,83.2 89.395,81.543 89.395,81.439 89.395,80.91 89.394,80.909 89.394,80.776 89.75,80.42 89.75,79.788 90.115,79.424 90.115,78.273 90.273,78.115 90.347,78.115 90.4,78.168 90.4,78.4 ; 87.796,81.5 88.106,81.19 88.285,81.011 88.285,79.715 88.8,79.2 ; 87.826,82.15 88.715,81.261 88.715,80.495 89.085,80.125 89.085,78.915 89.6,78.4 ; 87.87,60.813 90.4,63.343 90.4,64 ; 87.9,81.75 88.535,81.115 88.535,81.011 88.535,79.853 88.673,79.715 88.747,79.715 88.8,79.768 88.8,80 ; 87.93,82.4 88.965,81.365 88.965,80.599 89.335,80.229 89.335,79.053 89.473,78.915 89.547,78.915 89.6,78.968 89.6,79.2 ; 88.124,70.099 88.405,70.38 88.78,70.38 88.8,70.4 ; 89.745,63.452 89.745,64.271 89.925,64.451 89.925,65.925 90.4,66.4 ; v2@90.8,78 91.2,77.6 ; v2(90.846,66.845) 91.2,67.2 ; v2(90.846,67.645) 91.2,68 ; v2@90.865,65.226 v2(90.846,65.245) 91.2,65.6 ; v2(91.525,66.825) 91.575,66.825 91.95,67.2 92,67.2 ; 92.145,63.204 92.145,65.071 92.505,65.431 92.505,65.722 92.505,66.905 92.8,67.2 ; 92.325,62.976 92.325,64.997 92.603,65.275 92.744,65.275 92.8,65.331 92.8,65.6 ; 92.505,62.82 92.505,64.922 92.678,65.095 92.969,65.095 93.12,65.247 93.12,66.08 92.8,66.4 ; 92.765,62.66 92.765,64.346 92.825,64.406 92.825,64.775 92.8,64.8 ; v2(93.05,66.775) 93.294,67.019 93.364,67.019 93.545,67.2 93.6,67.2 ; 93.29,82.424 93.29,80.31 93.6,80 ; 93.6,76 v2@94,76.4 ; v2(93.898,66.003) 93.93,66.035 93.93,66.75 94.38,67.2 94.4,67.2 ; 93.925,62.425 93.925,65.173 94.105,65.353 94.105,65.722 94.25,65.868 94.25,66.239 94.4,66.389 94.4,66.4 ; v2(93.95,67.6) 94.35,68 94.4,68 ; 94.105,62.105 94.105,64.122 94.4,64.417 94.4,64.8 ; 94.4,61.975 94.4,64 ; 94.4,65.6 94.695,65.305 94.695,61.851 ; 95.045,81.28 95.045,80.533 94.915,80.403 94.915,79.882 95.2,79.597 95.2,79.2 ; 95.2,67.2 95.541,67.541 95.541,67.734 v2(95.6,67.793) ; 95.275,61.5 95.275,65 95.495,65.22 95.495,66.775 95.495,67.2 95.858,67.563 96.163,67.563 96.4,67.8 96.4,68.048 96,68.448 96,68.8 ; 95.455,61.383 95.455,64.913 95.675,65.133 95.675,66.875 96,67.2 ; 95.585,81.665 95.585,80.308 95.69,80.203 95.69,78.71 96,78.4 ; 95.635,61.266 95.635,64.838 96,65.203 96,65.6 ; 95.765,81.835 95.765,80.383 95.87,80.278 95.87,79.361 96,79.231 96,79.2 ; 95.833,61.167 95.833,64.576 96,64.743 96,64.8 ; 95.945,81.98 95.945,80.457 96.05,80.352 96.05,79.588 96.31,79.328 96.31,77.91 96,77.6 ; 96,66.4 96.295,66.105 96.295,64.62 96.081,64.406 96.081,61.118 ; 96,68 96,68.025 ; 96.125,82.2 96.125,80.532 96.23,80.427 96.23,79.663 96.49,79.403 96.49,78.8 96.49,78.71 96.8,78.4 ; 96.305,82.495 96.305,80.606 96.41,80.501 96.41,79.866 96.781,79.495 96.781,79.219 96.8,79.2 ; 96.315,60.815 96.315,64.385 96.475,64.545 96.475,66.875 96.8,67.2 ; 96.485,82.74 96.485,80.681 96.59,80.576 96.59,80.225 96.8,80.015 96.8,80 ; 97.6,78.762 98.09,79.252 98.09,80.244 98.245,80.399 98.245,83.761 ; 99.2,64.8 99.166,64.834 98.961,64.834 98.875,64.749 98.875,63.825 99.3,63.4 99.3,61.425 99.525,61.2 ; 99.2,65.6 99.192,65.592 99.192,65.381 99.035,65.224 98.997,65.224 98.625,64.852 98.625,63.721 99.05,63.296 99.05,61.321 99.275,61.096 ; 99.2,77.6 v2@99.6,78 ; 100,64 99.96,64.04 99.96,64.219 99.904,64.275 99.756,64.275 99.7,64.219 99.7,63.8 99.775,63.725 100.025,63.475 100.025,61.9 100.548,61.378 100.799,61.126 ; 100,64.8 99.96,64.76 99.96,64.581 99.904,64.525 99.622,64.525 99.45,64.354 99.45,63.696 99.775,63.371 99.775,61.796 100.361,61.211 100.549,61.022 ; 100.525,62.771 100.525,63.446 100.285,63.687 100.285,64.106 100.76,64.581 100.76,64.76 ; 100.76,64.04 100.709,63.989 100.588,63.989 100.535,63.937 100.535,63.79 100.775,63.55 100.775,62.875 ; 100.8,65.6 v2@101.138,65.262 ; 101.6,64 101.56,64.04 101.56,64.195 101.504,64.251 101.425,64.251 101.335,64.16 101.335,63.85 101.445,63.74 101.445,63.509 102,62.954 102.85,62.104 103.082,61.872 ; 101.6,64.8 101.56,64.76 101.56,64.585 101.5,64.525 101.346,64.525 101.085,64.264 101.085,63.746 101.195,63.637 101.195,63.543 101.195,63.406 101.75,62.85 102.6,62 102.832,61.768
  Top Layer w0.1: 81.172,76.29 85.72,76.29 86.01,76 86.4,76 ; 83.388,70.325 83.448,70.265 ; 83.838,62.335 84.635,63.132 84.635,63.791 85.244,64.4 86,64.4 86.4,64.8 ; 84.249,72 85.6,72 ; 84.29,68.41 84.65,68.41 ; 84.378,68.994 84.614,68.994 84.615,68.995 ; 84.412,68.8 85.6,68.8 ; 85.063,65.025 85.063,65.473 85.48,65.89 85.89,65.89 86.4,66.4 ; 85.199,73.085 85.394,73.28 85.792,73.28 86.162,72.91 86.236,72.91 86.346,72.8 86.4,72.8 ; 85.38,75.659 85.401,75.68 86.126,75.68 86.141,75.665 86.865,75.665 ; 85.459,75.469 85.48,75.49 85.79,75.49 85.805,75.475 86.115,75.475 ; v2(87.6,73.2) 88,73.6 ; 87.76,70.099 88.124,70.099 ; 87.914,74.011 89.989,74.011 90.4,73.6 ; 88,67.2 88,66.81 88.49,66.32 88.49,63.265 ; v2(88.4,72.4) 88.8,72.8 ; v2(88.4,73.2) 88.8,73.6 ; v2(88.4,74.8) 88.8,74.4 ; v2(88.4,75.6) 88.8,75.2 ; 88.722,63.227 88.722,64.601 89.31,65.189 89.31,65.72 89.6,66.01 89.6,66.4 ; 88.912,63.149 88.912,64.522 89.6,65.21 89.6,65.6 ; 89.102,63.07 89.102,64.302 89.6,64.8 ; v2(89.2,71.6) 89.6,72 ; v2(89.2,72.4) 89.6,72.8 ; v2(89.2,73.2) 89.6,73.6 ; v2(89.2,74.8) 89.6,74.4 ; v2(89.2,75.6) 89.6,75.2 ; v2(89.2,78) 89.6,77.6 ; v2(90.8,68.4) 91.2,68.8 ; v2(91.6,67.6) 92,68 ; v2(91.6,68.4) 92,68.8 ; v2(92.4,67.6) 92.8,68 ; v2(92.4,68.4) 92.8,68.8 ; 92.8,78.4 v2@93.2,78.8 ; v2(93.2,67.6) 93.6,68 ; v2(93.2,68.4) 93.6,68.8 ; v2(94,68.4) 94.4,68.8 ; 94.4,76.8 v2@94.8,77.2 ; v2(94.8,76.4) 95.2,76 ; v2(95.6,68.4) 96,68 ; 97.536,63.661 97.603,63.728 97.603,63.997 97.6,64 ; 97.6,64.8 97.6,64.439 97.89,64.149 97.89,63.88 97.823,63.813 97.823,63.637 97.756,63.569 ; 97.6,67.2 v2(98,66.8) ; 97.6,78.4 97.6,78.762 ; 98.35,61.975 98.08,62.245 98.08,64.88 98.48,65.28 98.48,65.466 98.4,65.546 98.4,65.6 ; 98.4,66.4 98.4,66.01 98.7,65.71 98.7,65.189 98.3,64.789 98.3,62.336 98.57,62.066 ; 98.4,67.2 98.643,66.957 98.643,66.857 v2(98.7,66.8) ; v2(100.5,72.4) 100.5,72.45 100.8,72.75 100.8,72.8
  Top Layer w0.11: v2(94.65,66) 94.606,66 94.662,66.055 94.855,66.055 95.2,66.4 ; v2(94.8,66.8) 94.8,67.602 95.198,68 95.2,68 ; v2(94.8,69.075) 95.2,68.8 ; 96.8,80.8 96.8,82.85
  Top Layer w0.2: 88.8,67.2 88.827,67.2 89.103,66.924 89.226,66.924 v2(89.264,66.886) ; v2(90.01,73.23) 90.01,73.21 90.4,72.82 90.4,72.8
  Bottom Layer w0.11: v2@94.8,66.752 v2(94.8,66.8) ; v2@95.6,67.709 v2(95.6,67.793)
  Bottom Layer w0.2: v2@89.264,66.858 v2(89.264,66.886)
  other v2: 101.15,65.275 94,76.4 94.8,77.2 90.8,78 99.6,78 93.2,78.8 87.6,80.42

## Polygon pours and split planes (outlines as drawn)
GND on Bottom Layer "GND_L04" (solid, pour order 154): 0.225,137.075 171.83,137.075 171.9,137.145 171.9,-0.225 0.025,-0.225
5V_STLK on Bottom Layer "5V_STLK_L04" (solid, pour order 149): 42.715,94.735 42.76,94.78 72.14,94.78 72.14,59.34 72.155,59.325 42.73,59.325
1V8 on Bottom Layer "1V8_L04" (solid, pour order 0): 84.939,76.533 84.939,85.255 86.38,85.255 86.38,82.845 86.37,82.843 92.23,82.843 92.23,77.2 90.71,77.2 90.71,81.299 87.934,81.299 87.934,79.63 87.966,79.598 89.365,79.159 89.365,76.533
VTT_DDR on Bottom Layer "VTT_DDR" (solid, remove dead copper, pour order 128): 137.7,66.642 137.543,66.484 127.825,66.484 127.825,64.325 139.922,64.325 140.35,64.7 140.35,69.07 139.795,69.07 139.795,70.03 140.35,70.03 140.35,70.725 140.125,70.725 140.075,70.775 140.075,71.7 140.125,71.75 140.975,71.75 142.075,72.85 142.075,74.08 142.27,74.275 142.825,74.275 143.45,74.9 144.5,74.9 145.5,75.9 145.5,82.4 143.15,84.75 136.8,84.75 136.45,84.4 136.45,82.9 136.725,82.625 142.625,82.625 143.05,82.2 143.05,79.3 134.75,79.3 134.75,77.625 134.8,77.575 134.825,77.6 141.375,77.6 141.375,76.65 141.8,76.225 141,75.425 141,74.925 140.25,74.925 139.6,74.275 139.6,72.625 137.7,72.625
VDD_DDR on Signal Layer 2 "VDD_DDR" (solid, remove dead copper, pour order 144): 49.219,81.75 53.077,81.75 53.236,81.591 53.236,79.166 52.541,78.471 49.219,78.471 48.216,77.468 46.918,77.468 46.246,78.14 46.246,85.378 50.853,89.985 96.44,89.985 105.249,81.176 137.988,81.046 141.8,77.26 141.8,66.1 130.3,66.1 122.21,58.01 113.238,58.01 111.348,59.899 106.149,59.901 98.8,67.25 98.8,67.634 97.684,68.75 96.606,68.75 96.265,69.091 96.265,70.637 95.376,71.527 95.376,72.916 97.65,75.19 97.65,76.018 97.85,76.217 97.85,80.725 97.149,80.725 97.14,80.716 95.32,82.536 93.76,84.095 49.539,84.095 49.219,83.775
GND on Signal Layer 2 "GND_L03" (solid, remove dead copper, pour order 152): 0,137 172,137 172,0 0,0
5V_STLK on Signal Layer 2 "5V_STLK_L03" (solid, pour order 150): 43.375,82.635 68.935,82.635 68.975,82.595 68.975,66.229 43.411,66.229
3V3 on Signal Layer 2 "3V3_L03" (solid, remove dead copper, pour order 146): 58,61.394 57.939,61.394 37.983,61.394 35.711,61.394 35.711,67.822 35.711,84.011 44.436,84.011 44.436,73.55 45.447,72.539 58,72.539
VDDGPU on Signal Layer 2 "VDDGPU" (solid, remove dead copper, pour order 127): 95.348,72.122 95.348,71.47 95.61,71.208 98.541,68.277 98.541,64.841 91.09,57.39 77.655,57.39 69.27,65.607 69.27,70.917 66.599,73.523 66.599,75.759 68.13,77.29 73.63,77.29 73.63,72.863 72.549,71.782 72.549,69.54 74.374,67.715 89.374,67.715 91.607,69.923 93.267,69.923 93.441,70.097 93.441,70.49 92.994,71.003 92.994,72.331 95.14,72.331
VDDIO on Signal Layer 2 "VDDIO_L03" (solid, remove dead copper, pour order 145): 93.852,70.39 93.235,69.772 91.585,69.772 89.378,67.564 74.378,67.564 72.553,69.389 72.553,71.646 73.945,73.038 93.024,73.038 93.852,72.21
VDDCORE on Signal Layer 2 "VDDCORE" (solid, remove dead copper, pour order 142): 93.118,75.605 93.118,77.055 91.173,79 73.745,79 73.745,73.019 93.843,73.019 93.843,74.83
VDDCPU on Signal Layer 2 "VDDCPU" (solid, remove dead copper, pour order 143): 97.516,75.448 94.844,72.776 94.833,72.775 92.631,72.775 92.631,76.645 92.631,77.532 91.618,78.545 66.455,78.545 66.455,80.62 66.505,80.67 66.175,81 60.143,81 60.055,80.912 59.116,81.85 49.319,81.85 49.219,81.75 49.219,83.775 50.843,85.4 59.717,85.4 60.603,84.513 60.603,84.5 93.355,84.5 97.516,80.339 97.516,76.697
1V8 on Signal Layer 2 "1V8" (solid, pour order 151): 60.675,96.6 60.675,93.472 101.693,93.472 101.752,83.21 115.76,83.21 117.725,85.175 117.725,96.6
GND on Top Layer "GND_L01" (solid, pour order 153): 0.178,137.102 0.303,136.977 171.973,136.977 171.973,-0.323 0.103,-0.323
3V3 on Top Layer "3V3" (solid, pour order 137): 44.387,68.548 44.562,68.373 50.91,68.373 52.212,69.675 52.212,70.523 44.588,70.523 44.387,70.323
5V_STLK on Top Layer "5V_STK" (solid, pour order 111): 54.01,75.62 54.667,75.62 54.85,75.803 54.85,75.463 54.367,74.98 54.01,74.98
VDDCPU on Top Layer "I_SENS_VDDCPU_P" (solid, pour order 133): 49.312,83.845 49.312,81.998 49.835,81.475 54.25,81.475 54.245,81.48 54.245,83.845
VDDCORE on Top Layer "I_SENS_VDDCORE_P" (solid, pour order 134): 72.507,84.74 75.389,81.858 75.389,75.631 75.394,75.626 73.94,75.626 73.395,76.171 73.395,80.872 73.022,81.245 71.375,81.245 67.015,81.245 67.005,84.74
VDDGPU on Top Layer "I_SENS_VDDGPU_P" (solid, pour order 135): 73.103,75.6 73.245,75.742 73.245,78.72 68.525,78.72 68.525,75.6
VDDIO on Top Layer "VDDIO" (solid, pour order 136): 62.495,78.77 62.495,80.568 63.03,81.103 63.212,81.103 63.65,80.664 63.65,80.123 62.95,79.423 62.95,78.77
NetL6_1 on Top Layer "NetL6_1" (solid, pour order 138): 64.875,73.863 65.338,73.4 66.6,73.4 66.6,71.1 66.598,71.098 65.301,71.098 65.301,72.722 64.875,73.148
GND on Signal Layer 1 "GND_L02" (solid, remove dead copper, pour order 99): -1,138 172,138 172,-1 -1,-1

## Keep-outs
Keep-Out Layer:
  lines w0.1: 133.661,133.38 142.561,133.38 142.561,135.53 133.661,135.53 133.661,133.38

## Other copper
Top Layer:
  rectangle net VDD_DDR: 47.155,73.8 50.125,75.6
  region net 5V_STLK: 56.73,80.524 56.631,80.425 56.275,80.425 cw(c56.275,80.775) 55.925,80.775 55.925,80.825 55.2,80.825 ccw(c55.2,80.75) 55.125,80.75 55.125,80.4 ccw(c55.327,80.397) 55.325,80.195 57.95,80.195 58.35,79.8 58.612,79.8 57.891,80.521 57.625,80.525
  region net 5V_STLK: 65.105,79.78 64.93,79.672 ccw(c65.063,79.473) 64.894,79.642 64.853,79.601 ccw(c65.113,79.342) 64.746,79.342 64.746,79.326 ccw(c65.101,79.326) 64.85,79.075 64.85,77.539 64.849,77.538 64.847,77.551 64.376,77.08 63.77,77.08 63.77,77.345 64.006,77.345 64.48,77.819 64.48,80.347 64.808,80.67 65.825,80.67 65.825,79.78
  region net GND: 56.4,79.685 56.307,79.685 ccw(c56.307,79.584) 56.235,79.655 55.955,79.375 ccw(c56.026,79.303) 55.925,79.303 55.925,78.975 56.425,78.975 cw(c56.823,78.982) 56.815,79.38 57.075,79.375 ccw(c57.075,79.423) 57.109,79.389 57.205,79.485
  region net GND: 63.725,76 63.65,75.925 63.572,75.925 cw(c63.572,75.798) 63.662,75.888 63.688,75.862 ccw(c63.778,75.952) 63.778,75.825 64.447,75.825 cw(c64.447,75.698) 64.537,75.788 64.6,75.725 64.729,75.854 cw(c64.78,75.803) 64.78,75.875
  region net NetL1_1: 59.072,81.875 ccw(c58.769,81.883) 58.978,82.102 58.955,82.125 58.955,82.187 59.026,82.194 ccw(c59.025,82.194) 59.025,82.195 59.175,82.075
  pour cut-out: 106.47,61.162 107.809,61.162 109.741,59.23 118.508,59.23 119.58,60.302 124.078,60.302 126.723,62.947 126.723,64.213 128.035,65.525 136.101,65.525 138.126,67.55 140.691,67.55 143.25,70.11 143.25,76.397 139.039,80.609 104.894,80.609 86.244,80.609 86.244,62.509 105.123,62.509
  region net 5V_STLK: 65.695,78.175 65.695,77.32 65.625,77.25 65.5,77.375 64.9,77.375 65.055,77.53 65.055,78.175
  region net 5V_STLK: 65.625,77.25 65.05,76.675 64.375,76.675 64.375,76.85 64.9,77.375
  region net 5V_STLK: 54.375,72.9 54.216,72.9 54.189,72.874 54.148,72.842 54.102,72.815 54.054,72.795 54.003,72.782 53.951,72.775 53.925,72.774 53.425,72.774 53.399,72.775 53.347,72.782 53.296,72.795 53.248,72.815 53.202,72.842 53.161,72.874 53.15,72.45 53.15,71.945 52.875,71.945 52.875,71.305 53.33,71.305 54.099,72.074 54.099,72.184 54.103,72.227 54.113,72.27 54.129,72.31 54.152,72.346 54.18,72.379 54.538,72.737
  region net 5V_STLK: 51.575,71.948 52.225,71.948 52.225,71.305 51.92,71.305 51.825,71.4 51.575,71.4
  region net 5V_STLK: 54.75,75.62 54.75,75.4 54.33,74.98 52.65,74.98 52.65,75.525 52.9,75.525 52.995,75.62
  region net 5V_STLK: 65.575,73.875 65.575,74.125 64.675,75.025 65.425,75.025 65.747,74.703
  region net 5V_STLK: 65.575,73.85 65.477,73.948 65.477,74.625 66.12,74.625 66.12,73.895 66.075,73.85 66.075,73.6 65.575,73.6
  region net 5V_STLK: 58.675,81.85 58.77,81.755 58.77,81.45 58.13,81.45 58.13,81.805 58.175,81.85 58.175,82.1 58.675,82.1
  region net 5V_STLK: 58.925,79.725 58.9,79.725 58.13,80.495 58.13,80.825 58.77,80.825 58.77,80.605 58.9,80.475 58.9,79.925
  region net 5V_STLK: 65.675,81 65.825,80.85 65.825,80.6 65.025,80.6 65.025,80.85 65.175,81 65.175,81.25 65.675,81.25
  region net 5V_STLK: 65.625,79.35 65.775,79.2 65.775,78.95 64.975,78.95 64.975,79.2 65.125,79.35 65.125,79.6 65.625,79.6
  region net 5V_STLK: 54.75,81.3 54.795,81.345 55.15,81.345 55.15,80.65 54.9,80.65 54.75,80.8 54.5,80.8 54.5,81.3
  region net GND: 51.575,72.75 51.62,72.705 52.18,72.705 52.225,72.75 52.225,73.345 51.92,73.345 51.825,73.25 51.575,73.25
  region net GND: 50.525,72.798 50.675,72.648 50.675,72.398 49.8,72.398 49.8,72.823 50.025,73.048 50.525,73.048
  region net GND: 50.525,72.798 50.375,72.648 50.375,72.398 51.2,72.398 51.2,72.873 51.025,73.048 50.525,73.048
  region net GND: 72.3,73.298 72.3,74.651 70.9,74.651 70.9,73.298
  region net GND: 59.525,87.425 59.675,87.275 59.675,87.025 58.8,87.025 58.8,87.45 59.025,87.675 59.525,87.675
  region net GND: 59.525,87.425 59.375,87.275 59.375,87.025 60.2,87.025 60.2,87.5 60.025,87.675 59.525,87.675
  region net GND: 57.675,87.425 57.825,87.275 57.825,87.025 56.95,87.025 56.95,87.45 57.175,87.675 57.675,87.675
  region net GND: 57.675,87.425 57.525,87.275 57.525,87.025 58.35,87.025 58.35,87.5 58.175,87.675 57.675,87.675
  region net GND: 56.1,81.323 56.297,81.52 56.75,81.52 56.75,80.63 56.293,80.63 56.1,80.823
  region net GND: 45.125,72.798 44.975,72.648 44.975,72.398 45.8,72.398 45.8,72.873 45.625,73.048 45.125,73.048
  region net GND: 45.125,72.798 45.275,72.648 45.275,72.398 44.4,72.398 44.4,72.823 44.625,73.048 45.125,73.048
  region net GND: 46.925,72.798 46.775,72.648 46.775,72.398 47.6,72.398 47.6,72.873 47.425,73.048 46.925,73.048
  region net GND: 46.925,72.798 47.075,72.648 47.075,72.398 46.2,72.398 46.2,72.823 46.425,73.048 46.925,73.048
  region net GND: 45.1,74.7 45.295,74.895 46.075,74.895 46.075,74.005 45.295,74.005 45.1,74.2
  region net GND: 48.725,72.798 48.575,72.648 48.575,72.398 49.4,72.398 49.4,72.873 49.225,73.048 48.725,73.048
  region net GND: 48.725,72.798 48.875,72.648 48.875,72.398 48,72.398 48,72.823 48.225,73.048 48.725,73.048
  region net GND: 57.075,79.375 56.74,79.375 56.74,79.385
  region net GND: 63.421,78.656 63.52,78.656 63.549,78.653 63.578,78.644 63.604,78.63 63.627,78.612 63.645,78.589 63.67,78.555 63.67,78.23 63.77,78.23 63.77,78.93 63.421,78.93
  region net GND: 53.425,72.952 53.23,73.147 53.23,73.602 54.12,73.602 54.12,73.147 53.925,72.952
  region net GND: 64.33,76.125 64.78,76.125 64.78,75.825 64.655,75.7 64.48,75.875 64.33,75.875
  region net GND: 45.1,77.3 45.295,77.495 46.075,77.495 46.075,76.605 45.295,76.605 45.1,76.8
  region net GND: 45.1,76 45.295,76.195 46.075,76.195 46.075,75.305 45.295,75.305 45.1,75.5
  region net GND: 51.45,85.873 51.645,85.678 51.645,85.223 50.755,85.223 50.755,85.678 50.95,85.873
  region net GND: 52.75,85.873 52.945,85.678 52.945,85.223 52.055,85.223 52.055,85.678 52.25,85.873
  region net GND: 54.05,85.873 54.245,85.678 54.245,85.223 53.355,85.223 53.355,85.678 53.55,85.873
  region net GND: 55.775,83.373 55.97,83.178 55.97,82.723 55.08,82.723 55.08,83.178 55.275,83.373
  region net GND: 55.825,87.425 55.675,87.275 55.675,87.025 56.5,87.025 56.5,87.5 56.325,87.675 55.825,87.675
  region net GND: 55.825,87.425 55.975,87.275 55.975,87.025 55.1,87.025 55.1,87.45 55.325,87.675 55.825,87.675
  region net GND: 70.45,80.825 70.645,80.63 70.645,79.775 69.755,79.775 69.755,80.63 69.95,80.825
  region net GND: 69.15,80.825 69.345,80.63 69.345,79.775 68.455,79.775 68.455,80.63 68.65,80.825
  region net GND: 67.7,86.825 67.895,86.63 67.895,85.775 67.005,85.775 67.005,86.63 67.2,86.825
  region net GND: 74.1,73.298 74.1,74.651 72.7,74.651 72.7,73.298
  region net GND: 70.5,73.298 70.5,74.651 69.1,74.651 69.1,73.298
  region net GND: 73.05,80.825 73.245,80.63 73.245,79.775 72.355,79.775 72.355,80.63 72.55,80.825
  region net GND: 71.75,80.825 71.945,80.63 71.945,79.775 71.055,79.775 71.055,80.63 71.25,80.825
  region net GND: 68.975,86.825 69.17,86.63 69.17,85.775 68.28,85.775 68.28,86.63 68.475,86.825
  region net GND: 70.25,86.825 70.445,86.63 70.445,85.775 69.555,85.775 69.555,86.63 69.75,86.825
  region net GND: 71.525,86.825 71.72,86.63 71.72,85.775 70.83,85.775 70.83,86.63 71.025,86.825
  region net GND: 67.8,78.325 67.605,78.13 66.75,78.13 66.75,79.02 67.605,79.02 67.8,78.825
  region net GND: 67.825,79.975 67.63,79.78 66.775,79.78 66.775,80.67 67.63,80.67 67.825,80.475
  region net GND: 68.002,74.375 67.807,74.18 67.5,74.18 67.5,75.07 67.975,75.07 68.17,74.875 68.17,74.375
  region net VDD_DDR: 47.795,77.615 47.795,77.731 48.148,78.084 48.148,79.215 47.795,79.215 47.155,79.215 46.798,79.215 46.798,78.019 47.155,77.662 47.155,77.238 47.795,77.238
  region net VDDIO: 73.08,70.835 73.08,70.719 72.727,70.366 72.727,69.235 73.08,69.235 73.72,69.235 74.077,69.235 74.077,70.431 73.72,70.788 73.72,71.212 73.08,71.212
  pour cut-out: 74.825,62.125 78.033,62.125 78.26,62.125 78.785,61.6 78.785,59.714 78.283,59.211 74.825,59.211
  pour cut-out: 68.455,77.45 67.395,77.45 67.395,75.35 68.455,75.35
  pour cut-out: 74.1,71.925 69.13,71.925 69.13,72.575 74.1,72.575
  pour cut-out: 67.4,73.075 66.6,73.075 66.6,70.975 67.4,70.975
  pour cut-out: 67.355,72.875 69.13,72.875 69.13,71.6 67.8,71.6
  pour cut-out: 52.3,81.605 52.3,80.545 54.4,80.545 54.4,81.605
  pour cut-out: 66.945,83.25 65.885,83.25 65.885,81.15 66.945,81.15
  region net NetL1_1: 59.495,82.275 59.15,81.93 58.695,82.385 58.695,84.075 59.495,84.075
  pour cut-out: 58.655,84.225 57.935,84.225 57.935,82.125 58.655,82.125
  region net NetL2_1: 65.15,82.225 65.15,81.45 65.015,81.45 64.325,80.76 64.325,78 63.85,77.525 63.525,77.525 63.525,77.675 63.614,77.675 63.77,77.831 63.95,78.011 64.005,78.094 64.025,78.191 64.025,78.742 64.07,78.85 64.07,79.01 64.009,79.157 63.897,79.269 63.77,79.322 63.75,79.325 63.75,83.102 64.098,83.45 65.015,83.45 65.15,83.315 65.15,83.2
  region net NetL5_1: 50.925,75.948 51.15,76.173 52.525,76.173 52.525,74.323 52.002,73.8 51.725,73.8 50.925,73.8
  pour cut-out: 49.995,73.65 51.055,73.65 51.055,75.75 49.995,75.75
  region net NetL4_1: 66.025,77.6 66.025,75.6 66.934,75.6 66.934,77.6
  region net NetL7_1: 54.375,70.35 54.075,70.05 53.3,70.05 53.3,70.95 54.375,72.02
  region net NetL3_1: 54.075,78.975 52.888,80.162 53.988,80.162 54.075,80.075 57.68,80.075 57.92,79.835 56.29,79.835 56.267,79.833 56.248,79.829 56.22,79.82 56.201,79.813 56.175,79.799 56.158,79.788 56.135,79.769 55.841,79.474 55.822,79.452 55.811,79.435 55.802,79.419 55.79,79.39 55.786,79.378 55.781,79.362 55.777,79.342 55.776,79.327 55.774,79.313 55.774,78.975
  region net NetL3_1: 55.283,80.045 55.254,80.048 55.225,80.057 55.151,80.089 55.125,80.103 55.103,80.122 55.047,80.18 55.028,80.203 55.014,80.229 54.988,80.294 54.981,80.316 54.958,80.347 54.933,80.367 54.897,80.391 54.851,80.4 54.075,80.4 54.075,79.263
  pour cut-out: 53,72.6 51.05,72.6 51.05,72.025 53,72.025
  pour cut-out: 44.4,70.773 51.05,70.773 51.05,71.573 44.4,71.573
  pour cut-out: 53.44,71.1 52.38,71.1 52.38,69 53.44,69
  pour cut-out: 75.75,68.05 75.75,65.25 78.28,65.25 78.28,68.05
  pour cut-out: 106.875,94 107.125,94.25 114,94.25 114.175,94.075 114.175,87.1 114,86.925 107.15,86.925 106.875,87.2
  text "1" at 134.025,133.811 h2
Signal Layer 1:
  text "2" at 135.309,133.811 h2
Signal Layer 2:
  text "5" at 140.661,133.833 h2
Bottom Layer:
  pour cut-out: 127.712,66.1 137.21,66.1 137.966,66.935 137.966,72.573 140.085,72.573 140.085,73.5 140.059,73.475 139.45,73.475 139.45,74.495 141.433,76.477 141.433,77.476 134.794,77.476 132.908,79.362 126.365,79.362 119.51,72.507 116.743,72.507 111.601,77.649 99.272,77.649 97.508,75.885 97.508,68.734 99.933,66.309 99.933,65.909 102.408,63.434 102.408,63.31 105.559,60.159 110.933,60.159 113.131,57.962 122.301,57.962 126.155,61.816 126.155,63.529 127.712,65.086
  text "6" at 142.16,133.822 h2

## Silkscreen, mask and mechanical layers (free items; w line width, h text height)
Top Overlay:
  text "J" at 39.706,118.242 h15
  text "VBAT" at 63.012,59.791 h1.2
